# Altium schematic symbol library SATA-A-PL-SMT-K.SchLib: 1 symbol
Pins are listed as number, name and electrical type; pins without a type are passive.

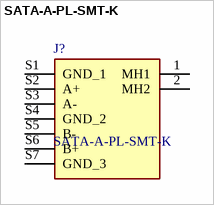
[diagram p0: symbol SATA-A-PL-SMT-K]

## SATA-A-PL-SMT-K
designator J?
Conn SATA PL 7 POS 1.27mm Solder RA SMD 7 Terminal 1 Port Tray/Tube; Manufacturer_Name: Adam Tech; Geometry.Height: 5.8928mm
footprint SATAAPLSMTK
pins: 1 MH1, 2 MH2, S1 GND_1, S2 A+, S3 A-, S4 GND_2, S5 B-, S6 B+, S7 GND_3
